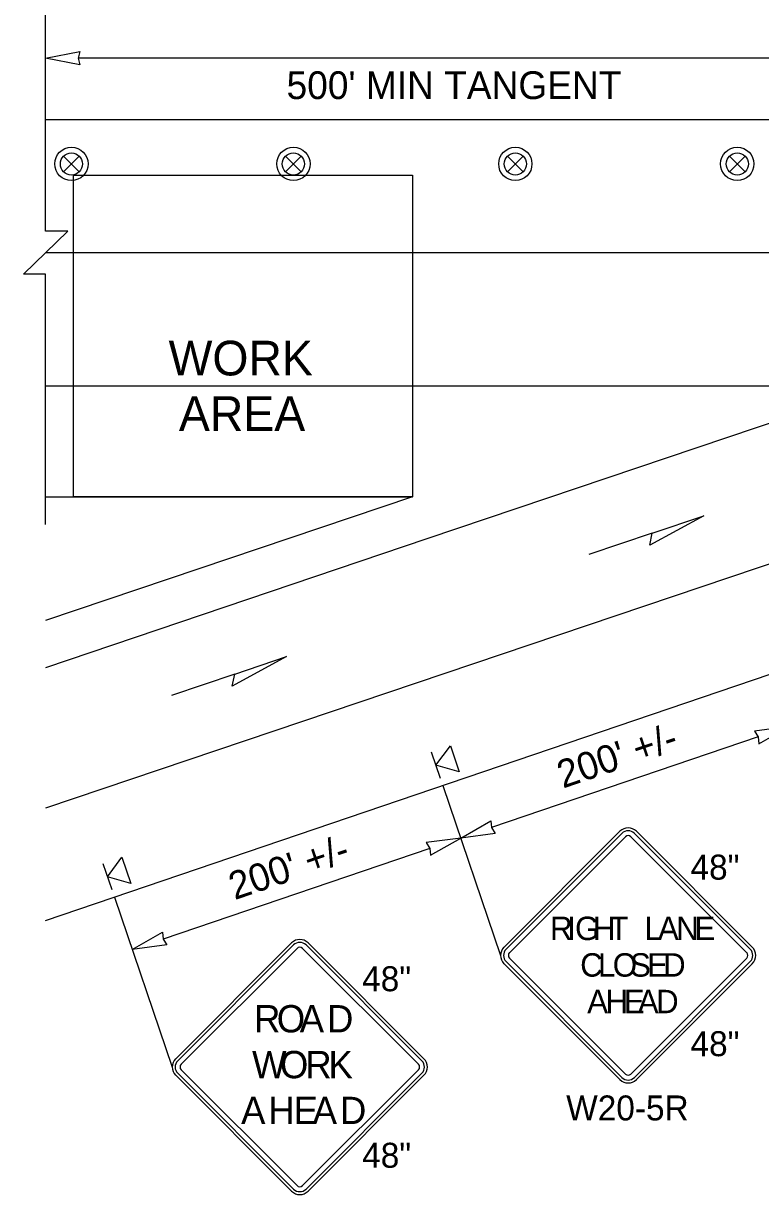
# Model space of a CAD drawing. Extents: x 99999 to 100116, y 99995 to 100013.
# Drawn here: x 100068.131 to 100070.257, y 100004.778 to 100008.156 of the extents above; entities that cross this region are included whole.
import ezdxf

# ---------------------------------------------------------------- set-up
doc = ezdxf.new("R2010")
doc.units = 0
for name, color, linetype in [('RD_MK_LineEdgeYellow', 7, 'Continuous'), ('RD_MK_LineLane', 7, 'Continuous'), ('TR_SN_ConstructionSigns', 7, 'Continuous'), ('TR_WZ_PortableSignMountBlk-Org', 7, 'Continuous'), ('TR_WZ_TrafficSafetyDrum', 7, 'Continuous'), ('TR_WZ_WorkAreaLabel', 7, 'Continuous'), ('TR_WZ_WorkZoneDetails', 7, 'Continuous'), ('TR_WZ_WorkZoneTextCurrent', 7, 'Continuous')]:
    doc.layers.add(name, color=color, linetype=linetype)

msp = doc.modelspace()

# ---------------------------------------------------------------- linework, layer by layer
at = {"layer": 'RD_MK_LineEdgeYellow'}
for p, q in [((100068.195, 100007.8789), (100075.43, 100007.8789)), ((100068.195, 100007.1109), (100069.2533, 100007.1109)), ((100070.6655, 100006.7269), (100068.195, 100005.8927)), ((100069.2943, 100006.6692), (100068.195, 100006.298))]:
    msp.add_line(p, q, dxfattribs=at)
at = {"layer": 'RD_MK_LineLane'}
msp.add_lwpolyline([(100075.43, 100007.4949), (100068.195, 100007.4949)], dxfattribs=at)
at = {"layer": 'TR_SN_ConstructionSigns'}
for p, q in [((100069.8509, 100005.8261), (100069.5168, 100005.492)), ((100069.8568, 100005.8202), (100069.5227, 100005.4861)), ((100069.5327, 100005.4761), (100069.8668, 100005.8102)), ((100069.8827, 100005.8102), (100070.2168, 100005.4761)), ((100070.2267, 100005.4861), (100069.8926, 100005.8202)), ((100070.2327, 100005.492), (100069.8986, 100005.8261)), ((100068.9041, 100005.5043), (100068.57, 100005.1702)), ((100069.2859, 100005.1702), (100068.9518, 100005.5043)), ((100068.91, 100005.4983), (100068.5759, 100005.1642)), ((100068.5859, 100005.1543), (100068.92, 100005.4884)), ((100068.9359, 100005.4884), (100069.27, 100005.1543)), ((100069.28, 100005.1642), (100068.9458, 100005.4983)), ((100069.5168, 100005.4443), (100069.8509, 100005.1102)), ((100069.5227, 100005.4503), (100069.8568, 100005.1162)), ((100069.8668, 100005.1261), (100069.5327, 100005.4602)), ((100070.2168, 100005.4602), (100069.8827, 100005.1261)), ((100069.8926, 100005.1162), (100070.2267, 100005.4503)), ((100069.8986, 100005.1102), (100070.2327, 100005.4443)), ((100068.92, 100004.8043), (100068.5859, 100005.1384)), ((100069.27, 100005.1384), (100068.9359, 100004.8043)), ((100068.57, 100005.1224), (100068.9041, 100004.7883)), ((100068.5759, 100005.1284), (100068.91, 100004.7943)), ((100068.9458, 100004.7943), (100069.28, 100005.1284)), ((100068.9518, 100004.7883), (100069.2859, 100005.1224))]:
    msp.add_line(p, q, dxfattribs=at)
for centre, radius, start, end in [((100069.8747, 100005.8023), 0.0338, 45, 135), ((100069.8747, 100005.8023), 0.0253, 45, 135), ((100069.8747, 100005.8023), 0.0113, 45, 135), ((100068.9279, 100005.4804), 0.0338, 45, 135), ((100068.9279, 100005.4804), 0.0253, 45, 135), ((100068.9279, 100005.4804), 0.0113, 45, 135), ((100069.5406, 100005.4682), 0.0338, 135, 225), ((100069.5406, 100005.4682), 0.0253, 135, 225), ((100069.5406, 100005.4682), 0.0113, 135, 225), ((100070.2088, 100005.4682), 0.0113, 315, 45), ((100070.2088, 100005.4682), 0.0253, 315, 45), ((100070.2088, 100005.4682), 0.0338, 315, 45), ((100068.5938, 100005.1463), 0.0338, 135, 225), ((100068.5938, 100005.1463), 0.0253, 135, 225), ((100069.2621, 100005.1463), 0.0253, 315, 45), ((100069.2621, 100005.1463), 0.0338, 315, 45), ((100068.5938, 100005.1463), 0.0113, 135, 225), ((100069.2621, 100005.1463), 0.0113, 315, 45), ((100069.8747, 100005.1341), 0.0338, 225, 315), ((100069.8747, 100005.1341), 0.0253, 225, 315), ((100069.8747, 100005.1341), 0.0113, 225, 315), ((100068.9279, 100004.8122), 0.0253, 225, 315), ((100068.9279, 100004.8122), 0.0113, 225, 315), ((100068.9279, 100004.8122), 0.0338, 225, 315)]:
    msp.add_arc(centre, radius, start, end, dxfattribs=at)
at = {"layer": 'TR_WZ_PortableSignMountBlk-Org'}
for p, q in [((100069.3333, 100005.9787), (100069.3076, 100006.0545)), ((100068.3865, 100005.6569), (100068.3608, 100005.7326))]:
    msp.add_line(p, q, dxfattribs=at)
for points in [[(100069.3205, 100006.0165), (100069.362, 100006.0729), (100069.3877, 100005.9972)], [(100068.3737, 100005.6947), (100068.4152, 100005.7511), (100068.4409, 100005.6753)]]:
    msp.add_lwpolyline(points, close=True, dxfattribs=at)
at = {"layer": 'TR_WZ_TrafficSafetyDrum'}
for p, q in [((100068.2468, 100007.7735), (100068.292, 100007.7283)), ((100068.292, 100007.7735), (100068.2468, 100007.7283)), ((100068.8868, 100007.7735), (100068.932, 100007.7283)), ((100068.932, 100007.7735), (100068.8868, 100007.7283)), ((100069.5268, 100007.7735), (100069.572, 100007.7283)), ((100069.572, 100007.7735), (100069.5268, 100007.7283)), ((100070.1668, 100007.7735), (100070.212, 100007.7283)), ((100070.212, 100007.7735), (100070.1668, 100007.7283))]:
    msp.add_line(p, q, dxfattribs=at)
for centre, radius in [((100068.2694, 100007.7509), 0.048), ((100068.2694, 100007.7509), 0.048), ((100068.9094, 100007.7509), 0.048), ((100068.9094, 100007.7509), 0.048), ((100069.5494, 100007.7509), 0.048), ((100069.5494, 100007.7509), 0.048), ((100070.1894, 100007.7509), 0.048), ((100070.1894, 100007.7509), 0.048), ((100068.2694, 100007.7509), 0.032), ((100068.9094, 100007.7509), 0.032), ((100069.5494, 100007.7509), 0.032), ((100070.1894, 100007.7509), 0.032)]:
    msp.add_circle(centre, radius, dxfattribs=at)
at = {"layer": 'TR_WZ_WorkZoneDetails'}
for p, q in [((100070.5087, 100008.0559), (100068.2887, 100008.0559)), ((100069.2533, 100007.1109), (100070.6024, 100007.1109)), ((100070.6024, 100007.1109), (100069.2943, 100006.6692)), ((100068.195, 100006.7909), (100069.2533, 100006.7909)), ((100069.2533, 100006.7909), (100068.195, 100006.4338)), ((100069.9441, 100006.6859), (100069.7613, 100006.6242)), ((100068.195, 100005.5689), (100070.6601, 100006.4069)), ((100068.7404, 100006.2795), (100068.5576, 100006.2178)), ((100070.2498, 100006.0985), (100069.4805, 100005.8369)), ((100069.3403, 100005.9583), (100069.5069, 100005.4682)), ((100069.303, 100005.7766), (100068.5337, 100005.5151)), ((100068.3935, 100005.6364), (100068.5601, 100005.1463))]:
    msp.add_line(p, q, dxfattribs=at)
msp.add_lwpolyline([(100068.195, 100006.7109), (100068.195, 100007.433), (100068.131, 100007.433), (100068.259, 100007.5569), (100068.195, 100007.5569), (100068.195, 100008.2789)], dxfattribs=at)
for points in [[(100068.195, 100008.0559), (100068.2933, 100008.0751), (100068.2887, 100008.0559), (100068.2933, 100008.0366)], [(100068.275, 100006.7909), (100068.275, 100007.7189), (100069.2533, 100007.7189), (100069.2533, 100006.7909)], [(100070.093, 100006.7362), (100069.9371, 100006.651), (100069.9441, 100006.6859)], [(100068.8893, 100006.3298), (100068.7333, 100006.2445), (100068.7404, 100006.2795)], [(100070.3386, 100006.1286), (100070.2393, 100006.1152), (100070.2498, 100006.0985), (100070.2517, 100006.0787)], [(100069.3918, 100005.8068), (100069.4786, 100005.8567), (100069.4805, 100005.8369), (100069.491, 100005.8202)], [(100069.3918, 100005.8068), (100069.2925, 100005.7934), (100069.303, 100005.7766), (100069.3049, 100005.7569)], [(100068.445, 100005.4849), (100068.5318, 100005.5348), (100068.5337, 100005.5151), (100068.5442, 100005.4983)]]:
    msp.add_lwpolyline(points, close=True, dxfattribs=at)

# ---------------------------------------------------------------- texts
at = {"layer": 'TR_SN_ConstructionSigns'}
for s, height, p in [('48"', 0.072, (100070.0545, 100005.6867)), ('R', 0.0675, (100069.6493, 100005.5125)), ('I', 0.0675, (100069.6986, 100005.5125)), ('G', 0.0675, (100069.7215, 100005.5125)), ('H', 0.0675, (100069.7728, 100005.5125)), ('T', 0.0675, (100069.8201, 100005.5125)), ('L', 0.0675, (100069.922, 100005.5125)), ('A', 0.0675, (100069.9605, 100005.5125)), ('N', 0.0675, (100070.0131, 100005.5125)), ('E', 0.0675, (100070.0658, 100005.5125)), ('C', 0.0675, (100069.7364, 100005.407)), ('L', 0.0675, (100069.7877, 100005.407)), ('O', 0.0675, (100069.8302, 100005.407)), ('S', 0.0675, (100069.8801, 100005.407)), ('E', 0.0675, (100069.9294, 100005.407)), ('D', 0.0675, (100069.9753, 100005.407)), ('48"', 0.072, (100069.1077, 100005.3649)), ('A', 0.0675, (100069.7566, 100005.3015)), ('H', 0.0675, (100069.8093, 100005.3015)), ('E', 0.0675, (100069.8619, 100005.3015)), ('A', 0.0675, (100069.9024, 100005.3015)), ('D', 0.0675, (100069.9551, 100005.3015)), ('R', 0.0788, (100068.796, 100005.2462)), ('O', 0.0788, (100068.8614, 100005.2462)), ('A', 0.0788, (100068.9276, 100005.2462)), ('D', 0.0788, (100069.0063, 100005.2462)), ('48"', 0.072, (100070.0545, 100005.1776)), ('W', 0.0788, (100068.7901, 100005.114)), ('O', 0.0788, (100068.8705, 100005.114)), ('R', 0.0788, (100068.9437, 100005.114)), ('K', 0.0788, (100069.0106, 100005.114)), ('W20-5R', 0.072, (100069.6961, 100004.9923)), ('A', 0.0788, (100068.7586, 100004.9818)), ('H', 0.0788, (100068.8374, 100004.9818)), ('E', 0.0788, (100068.9098, 100004.9818)), ('A', 0.0788, (100068.965, 100004.9818)), ('D', 0.0788, (100069.0437, 100004.9818)), ('48"', 0.072, (100069.1077, 100004.8558))]:
    msp.add_text(s, height=height, rotation=360, dxfattribs=at).set_placement(p)
at = {"layer": 'TR_WZ_WorkAreaLabel'}
for s, p in [('WORK', (100068.5496, 100007.1409)), ('AREA', (100068.5793, 100006.9809))]:
    msp.add_text(s, height=0.1, dxfattribs=at).set_placement(p)
at = {"layer": 'TR_WZ_WorkZoneTextCurrent'}
msp.add_text("500' MIN TANGENT", height=0.08, dxfattribs=at).set_placement((100068.8897, 100007.9379))
for p in [(100069.6866, 100005.9492), (100068.7398, 100005.6274)]:
    msp.add_text("200' +/-", height=0.08, rotation=18.775, dxfattribs=at).set_placement(p)

doc.saveas('drawing.dxf')
